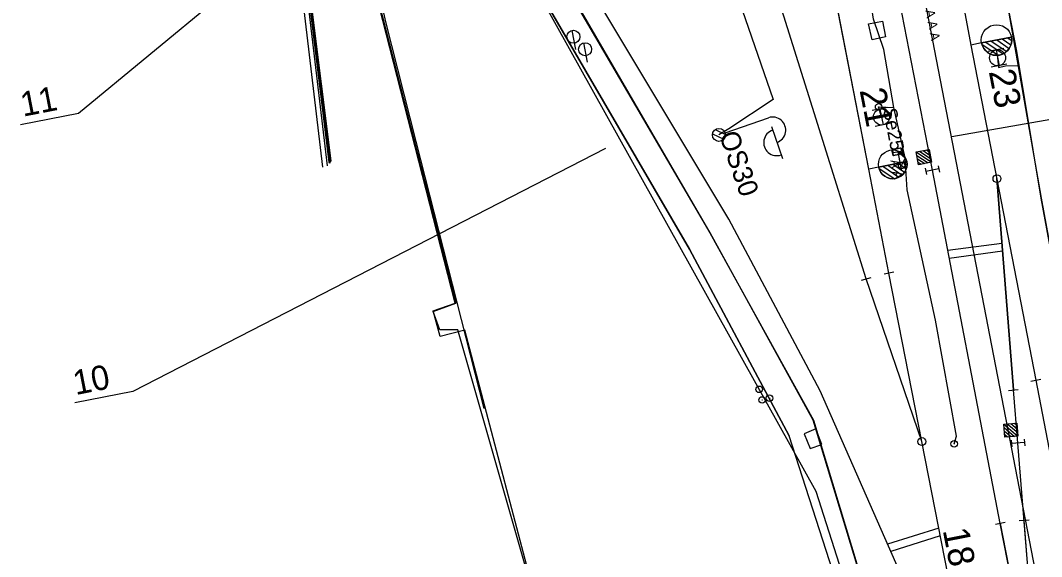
# Model space of a CAD drawing. Extents: x -545736 to -544888, y -1122892 to -1119128.
# Drawn here: x -545213 to -545134.9, y -1122299.5 to -1122258.5 of the extents above; entities that cross this region are included whole.
import ezdxf

# ---------------------------------------------------------------- set-up
doc = ezdxf.new("R2010")
doc.units = 0
for name, color, linetype in [('osvětlené plochy-hodnota-obrys', 7, 'Continuous'), ('so180602', 7, 'Continuous'), ('Vrstva 1', 7, 'Continuous'), ('Vrstva 1 - Koleje', 7, 'Continuous'), ('Vrstva 12', 7, 'Continuous'), ('Vrstva 13', 7, 'Continuous'), ('Vrstva 17', 7, 'Continuous'), ('Vrstva 2', 7, 'Continuous'), ('Vrstva 2 - Vyhybky', 7, 'Continuous'), ('Vrstva 25', 7, 'Continuous'), ('Vrstva 26', 7, 'Continuous'), ('Vrstva 27', 7, 'Continuous'), ('Vrstva 28', 7, 'Continuous'), ('Vrstva 28 - zabzar', 7, 'Continuous'), ('Vrstva 3', 7, 'Continuous'), ('Vrstva 3 - Lisy - Pocitaci body', 7, 'Continuous'), ('Vrstva 31', 7, 'Continuous'), ('Vrstva 39', 7, 'Continuous'), ('Vrstva 43', 7, 'Continuous'), ('Vrstva 47', 7, 'Continuous'), ('Vrstva 49', 7, 'Continuous'), ('Vrstva 51', 7, 'Continuous'), ('Vrstva 6 - Navesti', 7, 'Continuous'), ('Vrstva 63', 7, 'Continuous'), ('Vrstva 7', 7, 'Continuous')]:
    doc.layers.add(name, color=color, linetype=linetype)

msp = doc.modelspace()

# ---------------------------------------------------------------- linework, layer by layer
at = {"layer": 'osvětlené plochy-hodnota-obrys'}
for points in [[(-545141.742, -1122267.38), (-545105.592, -1122261.055), (-545104.447, -1122260.603), (-545110.322, -1122216.729), (-545115.194, -1122188.84), (-545124.338, -1122134.271), (-545128.334, -1122064.958), (-545124.139, -1121980.114), (-545129.58, -1121934.549), (-545137.864, -1121889.42)], [(-545132.033, -1122317.745), (-545201.844, -1121957.194), (-545188.779, -1121954.655), (-545199.189, -1121901.389)], [(-545144.58, -1122318.121), (-545152.135, -1122294.512), (-545180.579, -1122243.51)]]:
    msp.add_lwpolyline(points, dxfattribs=at)
at = {"layer": 'Vrstva 1'}
for points in [[(-545148.11, -1122269.864), (-545153.579, -1122241.752), (-545157.606, -1122221.016), (-545162.537, -1122195.725), (-545168.276, -1122166.312), (-545171.822, -1122147.996)], [(-545134.901, -1122312.911), (-545138.046, -1122296.967), (-545143.24, -1122269.949), (-545145.914, -1122256.175), (-545149.457, -1122237.965), (-545152.971, -1122219.909), (-545157.547, -1122196.44), (-545162.223, -1122172.446), (-545166.848, -1122148.879)], [(-545144.042, -1122290.699), (-545148.294, -1122278.255), (-545152.413, -1122265.168), (-545157.625, -1122248.574), (-545161.751, -1122235.479), (-545164.693, -1122226.098), (-545170.107, -1122208.853), (-545174.307, -1122195.178), (-545174.307, -1122195.178), (-545179.326, -1122176.026), (-545182.038, -1122162.981)], [(-545137.784, -1122322.523), (-545141.85, -1122311.027), (-545145.756, -1122300.605), (-545151.826, -1122286.809), (-545158.816, -1122273.694), (-545169.453, -1122255.952), (-545171.427, -1122252.524)], [(-545141.527, -1122303.562), (-545146.559, -1122277.83), (-545148.11, -1122269.864), (-545148.11, -1122269.864)], [(-545134.113, -1122322.61), (-545134.901, -1122312.911), (-545136.692, -1122290.81), (-545137.042, -1122286.746), (-545138.298, -1122270.6)]]:
    msp.add_lwpolyline(points, dxfattribs=at)
at = {"layer": 'Vrstva 1 - Koleje'}
for points in [[(-545176.383, -1122075.263), (-545174.481, -1122085.012), (-545172.568, -1122094.81), (-545170.661, -1122104.603), (-545170.158, -1122107.18), (-545168.724, -1122114.524), (-545166.809, -1122124.368), (-545164.912, -1122134.097), (-545162.998, -1122143.914), (-545161.094, -1122153.659), (-545159.194, -1122163.404), (-545157.278, -1122173.216), (-545155.337, -1122183.16), (-545153.457, -1122192.791), (-545151.544, -1122202.612), (-545149.632, -1122212.391), (-545147.716, -1122222.215), (-545145.801, -1122232.042), (-545143.903, -1122241.777), (-545142.834, -1122247.253), (-545141.885, -1122252.118), (-545140.814, -1122257.667), (-545140.289, -1122260.383)], [(-545140.289, -1122260.383), (-545135.323, -1122286.011), (-545134.062, -1122292.506), (-545132.157, -1122302.353)]]:
    msp.add_lwpolyline(points, dxfattribs=at)
at = {"layer": 'Vrstva 12'}
for p, q in [((-545145.69, -1122268.243), (-545145.636, -1122268.236)), ((-545146.351, -1122268.386), (-545146.272, -1122268.391)), ((-545146.217, -1122268.859), (-545146.234, -1122268.841))]:
    msp.add_line(p, q, dxfattribs=at)
for points in [[(-545146.351, -1122268.386), (-545145.636, -1122268.236), (-545145.503, -1122268.701), (-545146.234, -1122268.841)], [(-545146.272, -1122268.391), (-545145.69, -1122268.243), (-545145.534, -1122268.695), (-545146.217, -1122268.859)]]:
    msp.add_lwpolyline(points, close=True, dxfattribs=at)
at = {"layer": 'Vrstva 13'}
msp.add_line((-545189.35, -1122269.403), (-545189.337, -1122269.327), dxfattribs=at)
for points in [[(-545197.111, -1122206.804), (-545195.76, -1122220.542), (-545189.901, -1122269.711)], [(-545189.405, -1122269.346), (-545195.388, -1122220.384), (-545196.557, -1122206.786)], [(-545196.44, -1122206.768), (-545196.417, -1122206.745), (-545195.265, -1122220.377), (-545189.35, -1122269.403)], [(-545196.44, -1122206.768), (-545195.251, -1122220.408), (-545189.337, -1122269.327)], [(-545189.35, -1122269.403), (-545189.405, -1122269.346), (-545189.259, -1122269.232), (-545195.255, -1122221.308), (-545195.388, -1122220.384), (-545195.265, -1122220.377), (-545196.417, -1122206.745)]]:
    msp.add_lwpolyline(points, dxfattribs=at)
at = {"layer": 'Vrstva 17'}
msp.add_lwpolyline([(-545196.81, -1122206.576), (-545195.388, -1122220.378), (-545189.559, -1122269.609)], dxfattribs=at)
at = {"layer": 'Vrstva 2'}
for p, q in [((-545147.354, -1122269.715), (-545148.11, -1122269.864)), ((-545147.353, -1122269.714), (-545145.198, -1122269.296)), ((-545145.198, -1122269.296), (-545147.353, -1122269.715)), ((-545147.353, -1122269.715), (-545147.353, -1122269.714)), ((-545147.331, -1122269.796), (-545146.15, -1122270.593)), ((-545147.04, -1122269.654), (-545145.797, -1122270.491)), ((-545146.65, -1122269.578), (-545145.545, -1122270.322)), ((-545146.259, -1122269.502), (-545145.361, -1122270.108)), ((-545145.869, -1122269.426), (-545145.237, -1122269.852)), ((-545145.478, -1122269.35), (-545145.181, -1122269.55)), ((-545138.298, -1122270.6), (-545137.042, -1122286.746)), ((-545148.654, -1122278.36), (-545147.934, -1122278.15)), ((-545144.042, -1122290.699), (-545148.294, -1122278.255)), ((-545146.191, -1122277.758), (-545146.927, -1122277.902)), ((-545137.415, -1122286.785), (-545136.669, -1122286.707)), ((-545137.678, -1122296.896), (-545138.414, -1122297.038)), ((-545138.046, -1122296.967), (-545134.901, -1122312.911)), ((-545135.84, -1122296.707), (-545136.588, -1122296.767)), ((-545134.901, -1122312.911), (-545136.214, -1122296.737))]:
    msp.add_line(p, q, dxfattribs=at)
for points in [[(-545148.11, -1122269.864), (-545150.613, -1122256.998), (-545153.579, -1122241.752)], [(-545141.527, -1122303.562), (-545144.042, -1122290.699), (-545146.559, -1122277.83)]]:
    msp.add_lwpolyline(points, dxfattribs=at)
for centre, radius in [((-545146.269, -1122269.505), 1.097), ((-545138.298, -1122270.6), 0.3), ((-545144.042, -1122290.699), 0.3)]:
    msp.add_circle(centre, radius, dxfattribs=at)
msp.add_arc((-545146.275, -1122269.505), 1.098, 191.02857, 10.98942, dxfattribs=at)
at = {"layer": 'Vrstva 2 - Vyhybky'}
for p, q in [((-545139.482, -1122260.224), (-545140.289, -1122260.383)), ((-545139.481, -1122260.224), (-545137.183, -1122259.778)), ((-545137.183, -1122259.778), (-545139.481, -1122260.224)), ((-545139.481, -1122260.224), (-545139.481, -1122260.224)), ((-545139.458, -1122260.311), (-545138.199, -1122261.161)), ((-545139.148, -1122260.159), (-545137.822, -1122261.053)), ((-545138.731, -1122260.078), (-545137.553, -1122260.873)), ((-545138.314, -1122259.998), (-545137.357, -1122260.644)), ((-545137.898, -1122259.917), (-545137.225, -1122260.371)), ((-545137.481, -1122259.836), (-545137.165, -1122260.049)), ((-545135.716, -1122286.087), (-545134.93, -1122285.935))]:
    msp.add_line(p, q, dxfattribs=at)
msp.add_lwpolyline([(-545140.289, -1122260.383), (-545135.323, -1122286.011)], dxfattribs=at)
msp.add_circle((-545138.326, -1122260.001), 1.17, dxfattribs=at)
msp.add_arc((-545138.332, -1122260.001), 1.171, 191.01318, 10.97403, dxfattribs=at)
at = {"layer": 'Vrstva 25'}
for p, q in [((-545159.096, -1122267.09), (-545155.788, -1122265.946)), ((-545155.56, -1122266.608), (-545154.71, -1122269.065)), ((-545160.06, -1122267.17), (-545159.199, -1122267.589)), ((-545159.863, -1122266.849), (-545159.072, -1122267.234))]:
    msp.add_line(p, q, dxfattribs=at)
msp.add_circle((-545159.569, -1122267.253), 0.5, dxfattribs=at)
msp.add_circle((-545159.569, -1122267.253), 0.5, dxfattribs=at)
for centre, start, end in [((-545155.462, -1122266.891), 289.06905, 109.06905), ((-545155.147, -1122267.84), 108.36647, 289.77162)]:
    msp.add_arc(centre, 1, start, end, dxfattribs=at)
at = {"layer": 'Vrstva 26'}
msp.add_lwpolyline([(-545170.317, -1122221.476), (-545155.427, -1122264.551), (-545158.826, -1122266.782), (-545159.569, -1122267.253)], dxfattribs=at)
at = {"layer": 'Vrstva 27'}
for p, q in [((-545147.355, -1122265.085), (-545147.345, -1122265.135)), ((-545145.585, -1122269.605), (-545145.595, -1122269.555)), ((-545141.575, -1122290.855), (-545141.565, -1122290.905))]:
    msp.add_line(p, q, dxfattribs=at)
for centre in [(-545147.35, -1122265.11), (-545145.59, -1122269.58), (-545141.57, -1122290.88)]:
    msp.add_circle(centre, 0.25, dxfattribs=at)
at = {"layer": 'Vrstva 28'}
for p, q in [((-545156.511, -1122286.706), (-545156.461, -1122286.706)), ((-545156.286, -1122287.52), (-545156.236, -1122287.52)), ((-545155.713, -1122287.362), (-545155.689, -1122287.406))]:
    msp.add_line(p, q, dxfattribs=at)
for centre in [(-545156.486, -1122286.706), (-545156.261, -1122287.52), (-545155.701, -1122287.384)]:
    msp.add_circle(centre, 0.25, dxfattribs=at)
at = {"layer": 'Vrstva 28 - zabzar'}
for points in [[(-545131.71, -1122320.28), (-545130.72, -1122320.03), (-545127.65, -1122319.68), (-545126.87, -1122319.51), (-545127.17, -1122313.73), (-545127.74, -1122310.03), (-545128.49, -1122305.02), (-545132.37, -1122285.71), (-545134.29, -1122275.4), (-545134.91, -1122272.08), (-545136.78, -1122260.85), (-545137.78, -1122255.73), (-545136.19, -1122247.06), (-545136.38, -1122244.55), (-545136.66, -1122244.12), (-545137.71, -1122244.42), (-545138.82, -1122245.14)], [(-545141.57, -1122290.88), (-545141.38, -1122290.28), (-545143, -1122281.41), (-545145.18, -1122271.46), (-545145.33, -1122269.01), (-545146.2, -1122265.17), (-545146.96, -1122260.73), (-545147.74, -1122258.4), (-545148.13, -1122255.89), (-545150.11, -1122246.91)], [(-545138.25, -1122261.36), (-545138.19, -1122262.11), (-545137.64, -1122261.98), (-545136.6, -1122261.94)], [(-545147.13, -1122265.88), (-545147.35, -1122265.11), (-545146.2, -1122265.17)], [(-545145.86, -1122268.56), (-545145.33, -1122269.01), (-545145.59, -1122269.58)]]:
    msp.add_lwpolyline(points, dxfattribs=at)
at = {"layer": 'Vrstva 3'}
for p, q in [((-545143.778, -1122269.799), (-545143.683, -1122270.29)), ((-545142.749, -1122269.854), (-545143.731, -1122270.044)), ((-545142.797, -1122269.608), (-545142.702, -1122270.099)), ((-545137.212, -1122290.604), (-545137.169, -1122291.102)), ((-545136.194, -1122290.767), (-545137.19, -1122290.853)), ((-545136.215, -1122290.518), (-545136.172, -1122291.016))]:
    msp.add_line(p, q, dxfattribs=at)
at = {"layer": 'Vrstva 3 - Lisy - Pocitaci body'}
for p, q in [((-545137.762, -1122260.638), (-545138.972, -1122260.872)), ((-545138.367, -1122260.755), (-545138.133, -1122261.965)), ((-545137.528, -1122261.848), (-545138.738, -1122262.082)), ((-545146.643, -1122265.158), (-545147.852, -1122265.393)), ((-545147.248, -1122265.275), (-545147.012, -1122266.485)), ((-545146.408, -1122266.367), (-545147.617, -1122266.602)), ((-545144.476, -1122268.558), (-545143.306, -1122269.351)), ((-545144.426, -1122268.818), (-545143.566, -1122269.401)), ((-545144.376, -1122269.079), (-545143.827, -1122269.451)), ((-545144.216, -1122268.508), (-545143.356, -1122269.091)), ((-545143.955, -1122268.458), (-545143.406, -1122268.83)), ((-545143.695, -1122268.408), (-545143.456, -1122268.57)), ((-545144.326, -1122269.339), (-545144.087, -1122269.501)), ((-545137.769, -1122289.368), (-545136.687, -1122290.278)), ((-545137.505, -1122289.345), (-545136.71, -1122290.014)), ((-545137.241, -1122289.322), (-545136.733, -1122289.75)), ((-545136.977, -1122289.299), (-545136.755, -1122289.486)), ((-545137.746, -1122289.632), (-545136.951, -1122290.301)), ((-545137.724, -1122289.896), (-545137.216, -1122290.324)), ((-545137.701, -1122290.16), (-545137.48, -1122290.346))]:
    msp.add_line(p, q, dxfattribs=at)
for points in [[(-545143.494, -1122268.369), (-545143.306, -1122269.351), (-545144.288, -1122269.54), (-545144.476, -1122268.558)], [(-545136.773, -1122289.282), (-545136.687, -1122290.278), (-545137.683, -1122290.364), (-545137.769, -1122289.368)]]:
    msp.add_lwpolyline(points, close=True, dxfattribs=at)
for centre in [(-545138.249, -1122261.362), (-545147.129, -1122265.882)]:
    msp.add_circle(centre, 0.616, dxfattribs=at)
at = {"layer": 'Vrstva 31'}
msp.add_lwpolyline([(-545141.2, -1122230.63), (-545141.59, -1122230.77), (-545141.35, -1122232.04), (-545140.27, -1122237.06), (-545137.42, -1122240.57), (-545136.38, -1122244.55), (-545136.19, -1122247.06), (-545137.78, -1122255.73), (-545134.91, -1122272.08), (-545134.37, -1122274.99), (-545131.38, -1122275.36), (-545123.37, -1122274.09), (-545122.43, -1122272.99), (-545123.22, -1122267.88), (-545123.52, -1122265.67), (-545122.708, -1122265.909), (-545101.39, -1122261.81), (-545100.97, -1122261.92), (-545101.39, -1122262.57), (-545101.35, -1122263.26), (-545100.46, -1122269.21), (-545099.75, -1122273.09), (-545098.56, -1122275.85), (-545097.66, -1122283.01)], dxfattribs=at)
at = {"layer": 'Vrstva 39'}
for points in [[(-545185.865, -1122256.117), (-545185.865, -1122256.117), (-545179.709, -1122280.13), (-545179.709, -1122280.13)], [(-545179.748, -1122280.114), (-545185.848, -1122256.281)], [(-545167.508, -1122307.228), (-545172.867, -1122305.536), (-545179.022, -1122282.171), (-545180.906, -1122282.654), (-545181.439, -1122280.696), (-545179.748, -1122280.114)], [(-545167.413, -1122307.226), (-545172.809, -1122305.71), (-545179.554, -1122282.159), (-545180.922, -1122282.165), (-545181.433, -1122280.747), (-545179.709, -1122280.13)], [(-545179.709, -1122280.13), (-545179.709, -1122280.13)]]:
    msp.add_lwpolyline(points, dxfattribs=at)
at = {"layer": 'Vrstva 43'}
for p, q in [((-545170.524, -1122260.735), (-545170.806, -1122259.264)), ((-545169.623, -1122261.687), (-545169.909, -1122260.216))]:
    msp.add_line(p, q, dxfattribs=at)
for centre in [(-545170.712, -1122259.753), (-545169.814, -1122260.705)]:
    msp.add_circle(centre, 0.498, dxfattribs=at)
at = {"layer": 'Vrstva 47'}
for points in [[(-545147.062, -1122258.547), (-545146.834, -1122259.745), (-545147.849, -1122259.979), (-545148.124, -1122258.775)], [(-545153.059, -1122290.102), (-545152.603, -1122291.217), (-545151.703, -1122290.923), (-545152.157, -1122289.719)]]:
    msp.add_lwpolyline(points, close=True, dxfattribs=at)
at = {"layer": 'Vrstva 49'}
for points in [[(-545196.557, -1122206.786), (-545196.194, -1122208.73), (-545185.09, -1122258.613), (-545182.77, -1122267.763), (-545177.554, -1122288.159)], [(-545144.452, -1122314.254), (-545145.539, -1122311.532), (-545152.357, -1122289.072), (-545160.254, -1122274.736), (-545172.194, -1122254.201), (-545179.012, -1122242.195)], [(-545173.82, -1122255.403), (-545161.826, -1122275.996), (-545154.206, -1122290.262)]]:
    msp.add_lwpolyline(points, dxfattribs=at)
at = {"layer": 'Vrstva 51'}
msp.add_lwpolyline([(-545146.539, -1122314.39), (-545148.269, -1122308.579), (-545154.206, -1122290.262), (-545161.814, -1122275.984), (-545173.82, -1122255.403), (-545180.579, -1122243.51), (-545186.631, -1122230.199), (-545184.773, -1122229.485), (-545179.012, -1122242.195), (-545172.255, -1122254.252), (-545160.278, -1122274.749), (-545152.342, -1122289.056), (-545145.539, -1122311.532), (-545144.522, -1122314.31)], dxfattribs=at)
at = {"layer": 'Vrstva 6 - Navesti'}
for p, q in [((-545145.516, -1122268.494), (-545146.204, -1122268.626)), ((-545145.598, -1122269.921), (-545145.86, -1122268.56))]:
    msp.add_line(p, q, dxfattribs=at)
at = {"layer": 'Vrstva 63'}
for p, q in [((-545155.038, -1122221.442), (-545208.583, -1122265.609)), ((-545208.583, -1122265.609), (-545213.027, -1122266.473)), ((-545168.25, -1122268.297), (-545204.423, -1122286.865)), ((-545204.423, -1122286.865), (-545208.867, -1122287.729))]:
    msp.add_line(p, q, dxfattribs=at)
at = {"layer": 'Vrstva 7'}
for p, q in [((-545142.062, -1122276.078), (-545137.915, -1122275.52)), ((-545141.948, -1122276.668), (-545137.869, -1122276.119)), ((-545142.748, -1122297.318), (-545146.662, -1122298.545)), ((-545142.632, -1122297.911), (-545146.419, -1122299.098))]:
    msp.add_line(p, q, dxfattribs=at)

# ---------------------------------------------------------------- texts
at = {"layer": 'so180602'}
for s, p in [('11', (-545212.827, -1122265.866)), ('10', (-545208.806, -1122287.149))]:
    msp.add_text(s, height=1.875, rotation=10.99553, dxfattribs=at).set_placement(p)
at = {"layer": 'Vrstva 2'}
for s, rotation, p in [('21', 281.03048, (-545148.814, -1122263.837)), ('18', 281.02992, (-545142.452, -1122297.467))]:
    msp.add_text(s, height=2, rotation=rotation, dxfattribs=at).set_placement(p)
at = {"layer": 'Vrstva 2 - Vyhybky'}
msp.add_text('23', height=2, rotation=280.9936, dxfattribs=at).set_placement((-545138.929, -1122262.405))
at = {"layer": 'Vrstva 25'}
msp.add_text('OS30', height=1.5, rotation=289.06905, dxfattribs=at).set_placement((-545159.569, -1122267.253))
at = {"layer": 'Vrstva 6 - Navesti'}
for s, height, rotation, p in [('  A A A ', 0.7, 281.05508, (-545143.877, -1122257.234)), ('Se25', 1.05, 280.88191, (-545147.024, -1122265.304)), ('  A A ', 0.7, 280.88191, (-545146.547, -1122268.692))]:
    msp.add_text(s, height=height, rotation=rotation, dxfattribs=at).set_placement(p)

doc.saveas('drawing.dxf')
